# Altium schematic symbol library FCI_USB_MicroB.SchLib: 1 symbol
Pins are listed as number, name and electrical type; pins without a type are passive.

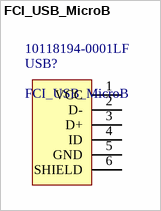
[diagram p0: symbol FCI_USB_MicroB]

## FCI_USB_MicroB
designator USB?  Manufacturer Part Number: 10118194-0001LF
FCI USB Micro B; Connector Type: USB - micro B; Number of Contacts: 5; Gender: Receptacle; Specifications: USB 2.0
footprint USB_Micro_B (FCI USB Micro B Connector)
pins: 1 VCC, 2 D-, 3 D+, 4 ID, 5 GND, 6 SHIELD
